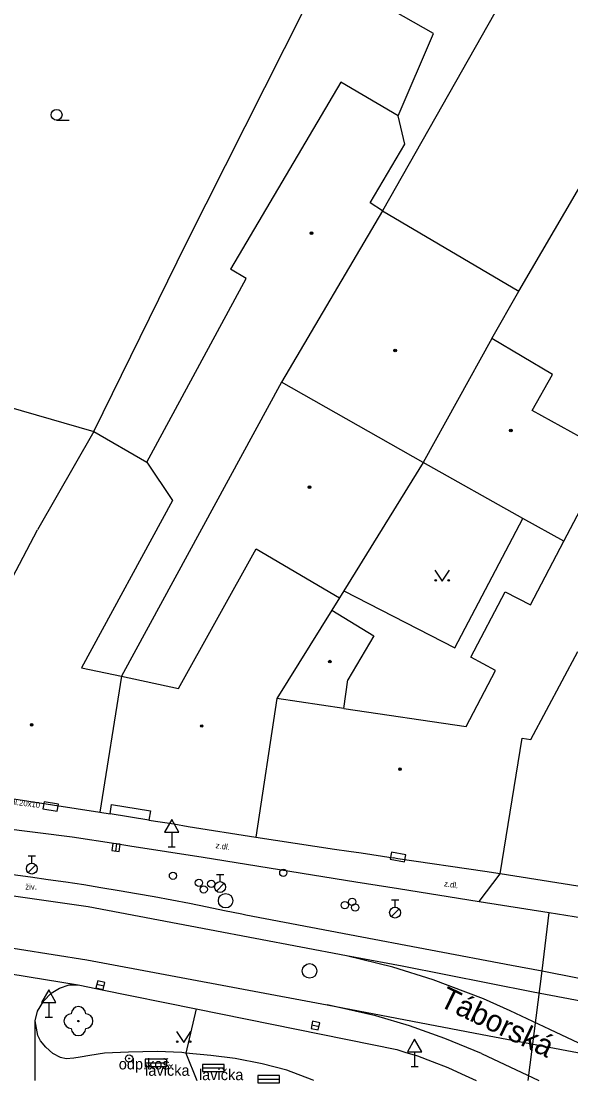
# Model space of a CAD drawing. Extents: x -596229 to -595156, y -1161237 to -1159376.
# Drawn here: x -596191.9 to -596153.9, y -1161235.6 to -1161162.4 of the extents above; entities that cross this region are included whole.
import ezdxf

# ---------------------------------------------------------------- set-up
doc = ezdxf.new("R2010")
doc.units = 0
for name, color, linetype in [('DOP - rozhrani ploch obecne', 7, 'Continuous'), ('Level 22', 7, 'Continuous'), ('Level 24', 7, 'Continuous'), ('Level 25', 7, 'Continuous'), ('Level 27', 7, 'Continuous'), ('Level 28', 7, 'Continuous'), ('Level 31', 7, 'Continuous'), ('Level 34', 7, 'Continuous'), ('Level 36', 7, 'Continuous'), ('Level 39', 7, 'Continuous'), ('Nazvy ulic', 7, 'Continuous'), ('Specificka linie pasportu komunikaci', 7, 'Continuous'), ('TM - budovy zdene_ betonove - NP', 7, 'Continuous'), ('TM - budovy zdene_ betonove - VP', 7, 'Continuous'), ('TM - komunikace - VP', 7, 'Continuous'), ('TM - letecke snimky - pomocna linie', 7, 'Continuous'), ('TM - MHD - osa koleji', 7, 'Continuous'), ('TM - popis povrchu', 7, 'Continuous'), ('TM - poznamka', 7, 'Continuous'), ('TM - rozhrani mezi zpev. plochami mezi sebou - VP', 7, 'Continuous'), ('TM - vstup do budovy - zdene_ betonove', 7, 'Continuous'), ('TM - vstup do budovy - zdene_ betonove  - shora neviditelny', 7, 'Continuous'), ('Vrstva 38', 7, 'Continuous')]:
    doc.layers.add(name, color=color, linetype=linetype)

msp = doc.modelspace()

# ---------------------------------------------------------------- linework, layer by layer
at = {"layer": 'DOP - rozhrani ploch obecne'}
for points in [[(-596141.86, -1161131.27), (-596166.93, -1161175.46)], [(-596157.54, -1161181), (-596131.83, -1161137.06)], [(-596180.46, -1161177.68), (-596171, -1161158.93)], [(-596186.84, -1161190.69), (-596180.46, -1161177.68)]]:
    msp.add_lwpolyline(points, dxfattribs=at)
at = {"layer": 'Level 22'}
msp.add_circle((-596187.91, -1161231.32), 0.05, dxfattribs=at)
for centre, start, end in [((-596187.91, -1161230.82), 0, 180), ((-596188.41, -1161231.32), 90, 270), ((-596187.41, -1161231.32), 270, 90), ((-596187.91, -1161231.82), 180, 0)]:
    msp.add_arc(centre, 0.5, start, end, dxfattribs=at)
at = {"layer": 'Level 24'}
for points in [[(-596190.362, -1161216.698), (-596189.374, -1161216.858), (-596189.295, -1161216.364), (-596190.282, -1161216.205)], [(-596165.336, -1161219.856), (-596166.318, -1161219.672), (-596166.411, -1161220.163), (-596165.428, -1161220.347)]]:
    msp.add_lwpolyline(points, close=True, dxfattribs=at)
at = {"layer": 'Level 25'}
for radius in [0.25, 0.0303]:
    msp.add_circle((-596184.42, -1161233.9), radius, dxfattribs=at)
at = {"layer": 'Level 27'}
for p, q in [((-596185.288, -1161219.102), (-596185.352, -1161219.598)), ((-596186.643, -1161228.781), (-596186.157, -1161228.899)), ((-596171.805, -1161231.58), (-596171.315, -1161231.68))]:
    msp.add_line(p, q, dxfattribs=at)
for points in [[(-596185.536, -1161219.07), (-596185.6, -1161219.566), (-596185.104, -1161219.63), (-596185.04, -1161219.134)], [(-596186.702, -1161229.024), (-596186.216, -1161229.142), (-596186.098, -1161228.656), (-596186.584, -1161228.538)], [(-596171.855, -1161231.825), (-596171.365, -1161231.925), (-596171.265, -1161231.435), (-596171.755, -1161231.335)]]:
    msp.add_lwpolyline(points, close=True, dxfattribs=at)
for centre in [(-596177.76, -1161223.02), (-596171.97, -1161227.86)]:
    msp.add_circle(centre, 0.5, dxfattribs=at)
at = {"layer": 'Level 28'}
for p, q in [((-596191.38, -1161219.935), (-596190.88, -1161219.935)), ((-596191.13, -1161220.435), (-596191.13, -1161219.935)), ((-596191.388, -1161221.082), (-596190.858, -1161220.552)), ((-596178.398, -1161222.352), (-596177.868, -1161221.822)), ((-596178.39, -1161221.205), (-596177.89, -1161221.205)), ((-596178.14, -1161221.705), (-596178.14, -1161221.205)), ((-596166.32, -1161222.965), (-596165.82, -1161222.965)), ((-596166.07, -1161223.465), (-596166.07, -1161222.965)), ((-596166.328, -1161224.112), (-596165.798, -1161223.582))]:
    msp.add_line(p, q, dxfattribs=at)
for centre, radius in [((-596191.13, -1161220.81), 0.375), ((-596181.39, -1161221.3), 0.25), ((-596179.6, -1161221.79), 0.25), ((-596178.75, -1161221.86), 0.25), ((-596178.14, -1161222.08), 0.375), ((-596179.27, -1161222.24), 0.25), ((-596169.54, -1161223.33), 0.25), ((-596169.03, -1161223.1), 0.25), ((-596168.82, -1161223.49), 0.25), ((-596166.07, -1161223.84), 0.375)]:
    msp.add_circle(centre, radius, dxfattribs=at)
at = {"layer": 'Level 31'}
msp.add_circle((-596173.78, -1161221.1), 0.25, dxfattribs=at)
at = {"layer": 'Level 34'}
for p, q in [((-596181.48, -1161218.292), (-596181.48, -1161219.31)), ((-596181.73, -1161219.31), (-596181.23, -1161219.31)), ((-596189.96, -1161230.032), (-596189.96, -1161231.05)), ((-596190.21, -1161231.05), (-596189.71, -1161231.05)), ((-596164.72, -1161233.432), (-596164.72, -1161234.45)), ((-596164.97, -1161234.45), (-596164.47, -1161234.45))]:
    msp.add_line(p, q, dxfattribs=at)
for points in [[(-596181.98, -1161218.292), (-596180.98, -1161218.292), (-596181.48, -1161217.426)], [(-596190.46, -1161230.032), (-596189.46, -1161230.032), (-596189.96, -1161229.166)], [(-596165.22, -1161233.432), (-596164.22, -1161233.432), (-596164.72, -1161232.566)]]:
    msp.add_lwpolyline(points, close=True, dxfattribs=at)
at = {"layer": 'Level 36'}
msp.add_line((-596189.42, -1161169.225), (-596188.545, -1161169.225), dxfattribs=at)
for points in [[(-596163.32, -1161200.24), (-596162.82, -1161200.99), (-596162.32, -1161200.24)], [(-596181.15, -1161232.04), (-596180.65, -1161232.79), (-596180.15, -1161232.04)]]:
    msp.add_lwpolyline(points, dxfattribs=at)
for centre, radius in [((-596189.42, -1161168.85), 0.375), ((-596163.27, -1161200.94), 0.05), ((-596162.371, -1161200.94), 0.05), ((-596181.1, -1161232.74), 0.05), ((-596180.201, -1161232.74), 0.05)]:
    msp.add_circle(centre, radius, dxfattribs=at)
at = {"layer": 'Level 39'}
for centre, radius in [((-596171.84, -1161177.01), 0.09), ((-596171.84, -1161177.01), 0.0398), ((-596166.06, -1161185.09), 0.09), ((-596166.06, -1161185.09), 0.0398), ((-596158.09, -1161190.61), 0.09), ((-596158.09, -1161190.61), 0.0398), ((-596171.97, -1161194.52), 0.09), ((-596171.97, -1161194.52), 0.0398), ((-596170.57, -1161206.54), 0.09), ((-596170.57, -1161206.54), 0.0398), ((-596191.14, -1161210.9), 0.09), ((-596191.14, -1161210.9), 0.0398), ((-596179.41, -1161210.98), 0.09), ((-596179.41, -1161210.98), 0.0398), ((-596165.73, -1161213.95), 0.09), ((-596165.73, -1161213.95), 0.0398)]:
    msp.add_circle(centre, radius, dxfattribs=at)
at = {"layer": 'Specificka linie pasportu komunikaci'}
for points in [[(-596160.26, -1161223.08), (-596158.81, -1161221.17)], [(-596155.93, -1161227.86), (-596155.43, -1161223.84)], [(-596156.885, -1161235.417), (-596155.93, -1161227.86)], [(-596179.78, -1161230.47), (-596180.5, -1161233.52)], [(-596180.5, -1161233.52), (-596179.74, -1161235.417)]]:
    msp.add_lwpolyline(points, dxfattribs=at)
at = {"layer": 'TM - budovy zdene_ betonove - NP'}
for points in [[(-596185.73, -1161217.03), (-596185.62, -1161216.38)], [(-596182.95, -1161216.82), (-596183.06, -1161217.47)]]:
    msp.add_lwpolyline(points, dxfattribs=at)
at = {"layer": 'TM - budovy zdene_ betonove - VP'}
for points in [[(-596169.82, -1161166.59), (-596177.43, -1161179.48)], [(-596165.85, -1161168.93), (-596169.82, -1161166.59)], [(-596165.4, -1161170.87), (-596165.85, -1161168.93)], [(-596167.79, -1161174.92), (-596165.4, -1161170.87)], [(-596166.93, -1161175.46), (-596167.79, -1161174.92)], [(-596166.93, -1161175.46), (-596173.9, -1161187.27)], [(-596166.93, -1161175.46), (-596157.54, -1161181)], [(-596183.19, -1161192.8), (-596176.34, -1161180.13)], [(-596176.34, -1161180.13), (-596177.43, -1161179.48)], [(-596159.39, -1161184.26), (-596157.54, -1161181)], [(-596208.82, -1161184.33), (-596186.84, -1161190.69)], [(-596159.39, -1161184.26), (-596164.13, -1161192.82)], [(-596155.21, -1161186.75), (-596159.39, -1161184.26)], [(-596173.9, -1161187.27), (-596184.93, -1161207.55)], [(-596164.13, -1161192.82), (-596173.9, -1161187.27)], [(-596156.61, -1161189.23), (-596155.21, -1161186.75)], [(-596153.27, -1161191.06), (-596156.61, -1161189.23)], [(-596186.84, -1161190.69), (-596190.74, -1161197.45)], [(-596186.84, -1161190.69), (-596183.19, -1161192.8)], [(-596154.43, -1161198.24), (-596151.23, -1161192.18)], [(-596183.19, -1161192.8), (-596181.42, -1161195.44)], [(-596164.13, -1161192.82), (-596169.6, -1161201.66)], [(-596157.25, -1161196.67), (-596164.13, -1161192.82)], [(-596181.42, -1161195.44), (-596187.69, -1161206.96)], [(-596154.43, -1161198.24), (-596157.25, -1161196.67)], [(-596195.19, -1161205.92), (-596190.74, -1161197.45)], [(-596156.74, -1161202.62), (-596154.43, -1161198.24)], [(-596181, -1161208.39), (-596175.65, -1161198.77)], [(-596175.65, -1161198.77), (-596169.91, -1161202.15)], [(-596169.6, -1161201.66), (-596169.91, -1161202.15)], [(-596160.84, -1161206.23), (-596158.48, -1161201.73)], [(-596158.48, -1161201.73), (-596156.74, -1161202.62)], [(-596169.91, -1161202.15), (-596170.44, -1161203)], [(-596170.44, -1161203), (-596174.22, -1161209.09)], [(-596170.44, -1161203), (-596167.53, -1161204.77)], [(-596167.53, -1161204.77), (-596169.32, -1161207.8)], [(-596159.14, -1161207.16), (-596160.84, -1161206.23)], [(-596156.7, -1161211.91), (-596153.47, -1161205.85)], [(-596187.69, -1161206.96), (-596184.93, -1161207.55)], [(-596161.17, -1161211.01), (-596159.14, -1161207.16)], [(-596184.93, -1161207.55), (-596186.43, -1161216.92)], [(-596184.93, -1161207.55), (-596181, -1161208.39)], [(-596169.61, -1161209.77), (-596169.32, -1161207.8)], [(-596174.22, -1161209.09), (-596175.67, -1161218.63)], [(-596169.61, -1161209.77), (-596174.22, -1161209.09)], [(-596169.61, -1161209.77), (-596161.17, -1161211.01)], [(-596158.81, -1161221.17), (-596157.3, -1161211.82)], [(-596157.3, -1161211.82), (-596156.7, -1161211.91)], [(-596192.96, -1161215.9), (-596186.43, -1161216.92)], [(-596186.43, -1161216.92), (-596185.73, -1161217.03)], [(-596183.06, -1161217.47), (-596185.73, -1161217.03)], [(-596183.06, -1161217.47), (-596181.34, -1161217.73)], [(-596180.34, -1161217.9), (-596175.67, -1161218.63)], [(-596175.67, -1161218.63), (-596170.26, -1161219.46)], [(-596169.25, -1161219.6), (-596168.4, -1161219.72)], [(-596158.81, -1161221.17), (-596159.88, -1161221.01), (-596165.88, -1161220.13), (-596166.2, -1161220.07)], [(-596148.1, -1161222.87), (-596158.81, -1161221.17)]]:
    msp.add_lwpolyline(points, dxfattribs=at)
at = {"layer": 'TM - komunikace - VP'}
for points in [[(-596193.26, -1161217.99), (-596188.34, -1161218.61), (-596185.33, -1161219.07), (-596184.36, -1161219.23), (-596179.31, -1161220.02)], [(-596179.31, -1161220.02), (-596168.77, -1161221.72), (-596165.83, -1161222.18), (-596160.26, -1161223.08)], [(-596160.26, -1161223.08), (-596155.43, -1161223.84)], [(-596155.43, -1161223.84), (-596152.57, -1161224.3), (-596144, -1161225.64)], [(-596190.89, -1161231.31), (-596190.74, -1161230.64), (-596190.29, -1161229.92), (-596189.79, -1161229.4), (-596189.22, -1161229.05), (-596188.56, -1161228.83), (-596187.94, -1161228.81)], [(-596187.94, -1161228.81), (-596187.16, -1161228.98)], [(-596187.16, -1161228.98), (-596186.4, -1161229.13), (-596179.78, -1161230.47)], [(-596179.78, -1161230.47), (-596165.94, -1161233.27)], [(-596180.5, -1161233.52), (-596180.79, -1161233.49), (-596182.47, -1161233.42), (-596184.47, -1161233.45), (-596186.11, -1161233.54), (-596187.13, -1161233.68), (-596187.79, -1161233.8), (-596188.24, -1161233.87), (-596188.75, -1161233.91), (-596189.14, -1161233.82), (-596189.67, -1161233.56), (-596190.17, -1161233.12), (-596190.53, -1161232.68), (-596190.72, -1161232.31), (-596190.89, -1161231.31)], [(-596171.666, -1161235.417), (-596171.78, -1161235.37), (-596173.53, -1161234.71), (-596175.23, -1161234.26), (-596177.09, -1161233.9), (-596178.77, -1161233.68), (-596180.5, -1161233.52)], [(-596165.94, -1161233.27), (-596165.39, -1161233.45), (-596164.53, -1161233.72), (-596163.51, -1161234.1), (-596162.44, -1161234.52), (-596161.49, -1161234.95), (-596160.486, -1161235.417)]]:
    msp.add_lwpolyline(points, dxfattribs=at)
at = {"layer": 'TM - letecke snimky - pomocna linie'}
for points in [[(-596165.85, -1161168.93), (-596163.42, -1161163.24), (-596171, -1161158.93)], [(-596169.6, -1161201.66), (-596161.95, -1161205.6), (-596157.25, -1161196.67)], [(-596204.71, -1161220.14), (-596199.38, -1161220.48), (-596197.32, -1161220.64), (-596196.11, -1161220.77), (-596194.89, -1161220.91), (-596193.66, -1161221.06), (-596192.44, -1161221.21), (-596191.21, -1161221.38), (-596189.99, -1161221.55), (-596188.77, -1161221.72), (-596187.55, -1161221.91), (-596186.36, -1161222.1), (-596185.11, -1161222.31), (-596183.9, -1161222.52), (-596182.68, -1161222.74), (-596181.47, -1161222.95), (-596180.26, -1161223.19), (-596179.04, -1161223.44), (-596177.84, -1161223.69), (-596176.63, -1161223.93), (-596176.36, -1161223.99), (-596169.21, -1161225.34), (-596158.03, -1161227.46), (-596155.93, -1161227.86)], [(-596155.93, -1161227.86), (-596141.76, -1161230.65), (-596135.72, -1161231.66), (-596129.28, -1161232.06), (-596125.83, -1161231.97), (-596122.3, -1161231.85), (-596119.14, -1161231.52), (-596114.37, -1161230.84)]]:
    msp.add_lwpolyline(points, dxfattribs=at)
at = {"layer": 'TM - MHD - osa koleji'}
for points in [[(-596178.87, -1161225.02), (-596187.25, -1161223.44), (-596193.53, -1161222.54), (-596201, -1161221.64), (-596207.73, -1161221.15), (-596212.98, -1161221.01), (-596218.24, -1161220.88), (-596223.76, -1161220.95), (-596228.22, -1161221.098)], [(-596228.22, -1161224.665), (-596221.62, -1161224.47), (-596214.71, -1161224.47), (-596207.18, -1161224.82), (-596200.13, -1161225.37), (-596194.33, -1161225.99), (-596187.34, -1161227.09)], [(-596141.41, -1161232.15), (-596150.34, -1161230.49), (-596156.55, -1161229.32), (-596165.59, -1161227.53), (-596169.41, -1161226.83), (-596178.87, -1161225.02)], [(-596151.04, -1161233.94), (-596155.4, -1161231.89), (-596158.12, -1161230.61), (-596159.97, -1161229.78), (-596163.45, -1161228.47), (-596166.22, -1161227.6), (-596169.41, -1161226.83)], [(-596187.34, -1161227.09), (-596170.76, -1161230.19), (-596160.07, -1161232.25), (-596155.43, -1161233.11), (-596151.04, -1161233.94), (-596145.55, -1161234.99), (-596143.78, -1161235.32)], [(-596160.1, -1161233.56), (-596162.63, -1161232.51), (-596165.08, -1161231.65), (-596167.39, -1161230.96), (-596170.76, -1161230.19)], [(-596160.1, -1161233.56), (-596156.148, -1161235.417)]]:
    msp.add_lwpolyline(points, dxfattribs=at)
at = {"layer": 'TM - rozhrani mezi zpev. plochami mezi sebou - VP'}
for points in [[(-596198.5, -1161227.1), (-596187.94, -1161228.81)], [(-596190.89, -1161235.417), (-596190.89, -1161231.31)]]:
    msp.add_lwpolyline(points, dxfattribs=at)
at = {"layer": 'TM - vstup do budovy - zdene_ betonove'}
for points in [[(-596181.34, -1161217.73), (-596180.34, -1161217.9)], [(-596170.26, -1161219.46), (-596169.25, -1161219.6)], [(-596168.4, -1161219.72), (-596166.2, -1161220.07)]]:
    msp.add_lwpolyline(points, dxfattribs=at)
at = {"layer": 'TM - vstup do budovy - zdene_ betonove  - shora neviditelny'}
msp.add_lwpolyline([(-596185.62, -1161216.38), (-596182.95, -1161216.82)], dxfattribs=at)
at = {"layer": 'Vrstva 38'}
for p, q in [((-596181.814, -1161233.94), (-596183.314, -1161233.94)), ((-596183.314, -1161233.94), (-596183.314, -1161234.44)), ((-596183.314, -1161234.19), (-596181.814, -1161234.19)), ((-596181.814, -1161234.44), (-596181.814, -1161233.94)), ((-596183.314, -1161234.44), (-596181.814, -1161234.44)), ((-596177.864, -1161234.3), (-596179.364, -1161234.3)), ((-596179.364, -1161234.3), (-596179.364, -1161234.8)), ((-596179.364, -1161234.55), (-596177.864, -1161234.55)), ((-596179.364, -1161234.8), (-596177.864, -1161234.8)), ((-596177.864, -1161234.8), (-596177.864, -1161234.3)), ((-596174.034, -1161235.07), (-596175.534, -1161235.07)), ((-596175.534, -1161235.07), (-596175.534, -1161235.57)), ((-596175.534, -1161235.32), (-596174.034, -1161235.32)), ((-596175.534, -1161235.57), (-596174.034, -1161235.57)), ((-596174.034, -1161235.57), (-596174.034, -1161235.07))]:
    msp.add_line(p, q, dxfattribs=at)

# ---------------------------------------------------------------- texts
at = {"layer": 'Nazvy ulic'}
msp.add_text('Táborská', height=1.5, rotation=334.3464, dxfattribs=at).set_placement((-596163.115, -1161230.245))
at = {"layer": 'TM - popis povrchu'}
for s, rotation, p in [('b.dl.20x10', 353, (-596193.03, -1161216.33)), ('z.dl.', 351, (-596178.47, -1161219.39)), ('z.dl.', 351, (-596162.71, -1161222.02))]:
    msp.add_text(s, height=0.4, rotation=rotation, dxfattribs=at).set_placement(p)
msp.add_text('živ.', height=0.4, dxfattribs=at).set_placement((-596191.58, -1161222.26))
at = {"layer": 'TM - poznamka'}
for s, p in [('odp.koš', (-596185.13, -1161234.65)), ('lavička', (-596183.31, -1161235.09)), ('lavička', (-596179.6, -1161235.39))]:
    msp.add_text(s, height=0.75, dxfattribs=at).set_placement(p)

doc.saveas('drawing.dxf')
